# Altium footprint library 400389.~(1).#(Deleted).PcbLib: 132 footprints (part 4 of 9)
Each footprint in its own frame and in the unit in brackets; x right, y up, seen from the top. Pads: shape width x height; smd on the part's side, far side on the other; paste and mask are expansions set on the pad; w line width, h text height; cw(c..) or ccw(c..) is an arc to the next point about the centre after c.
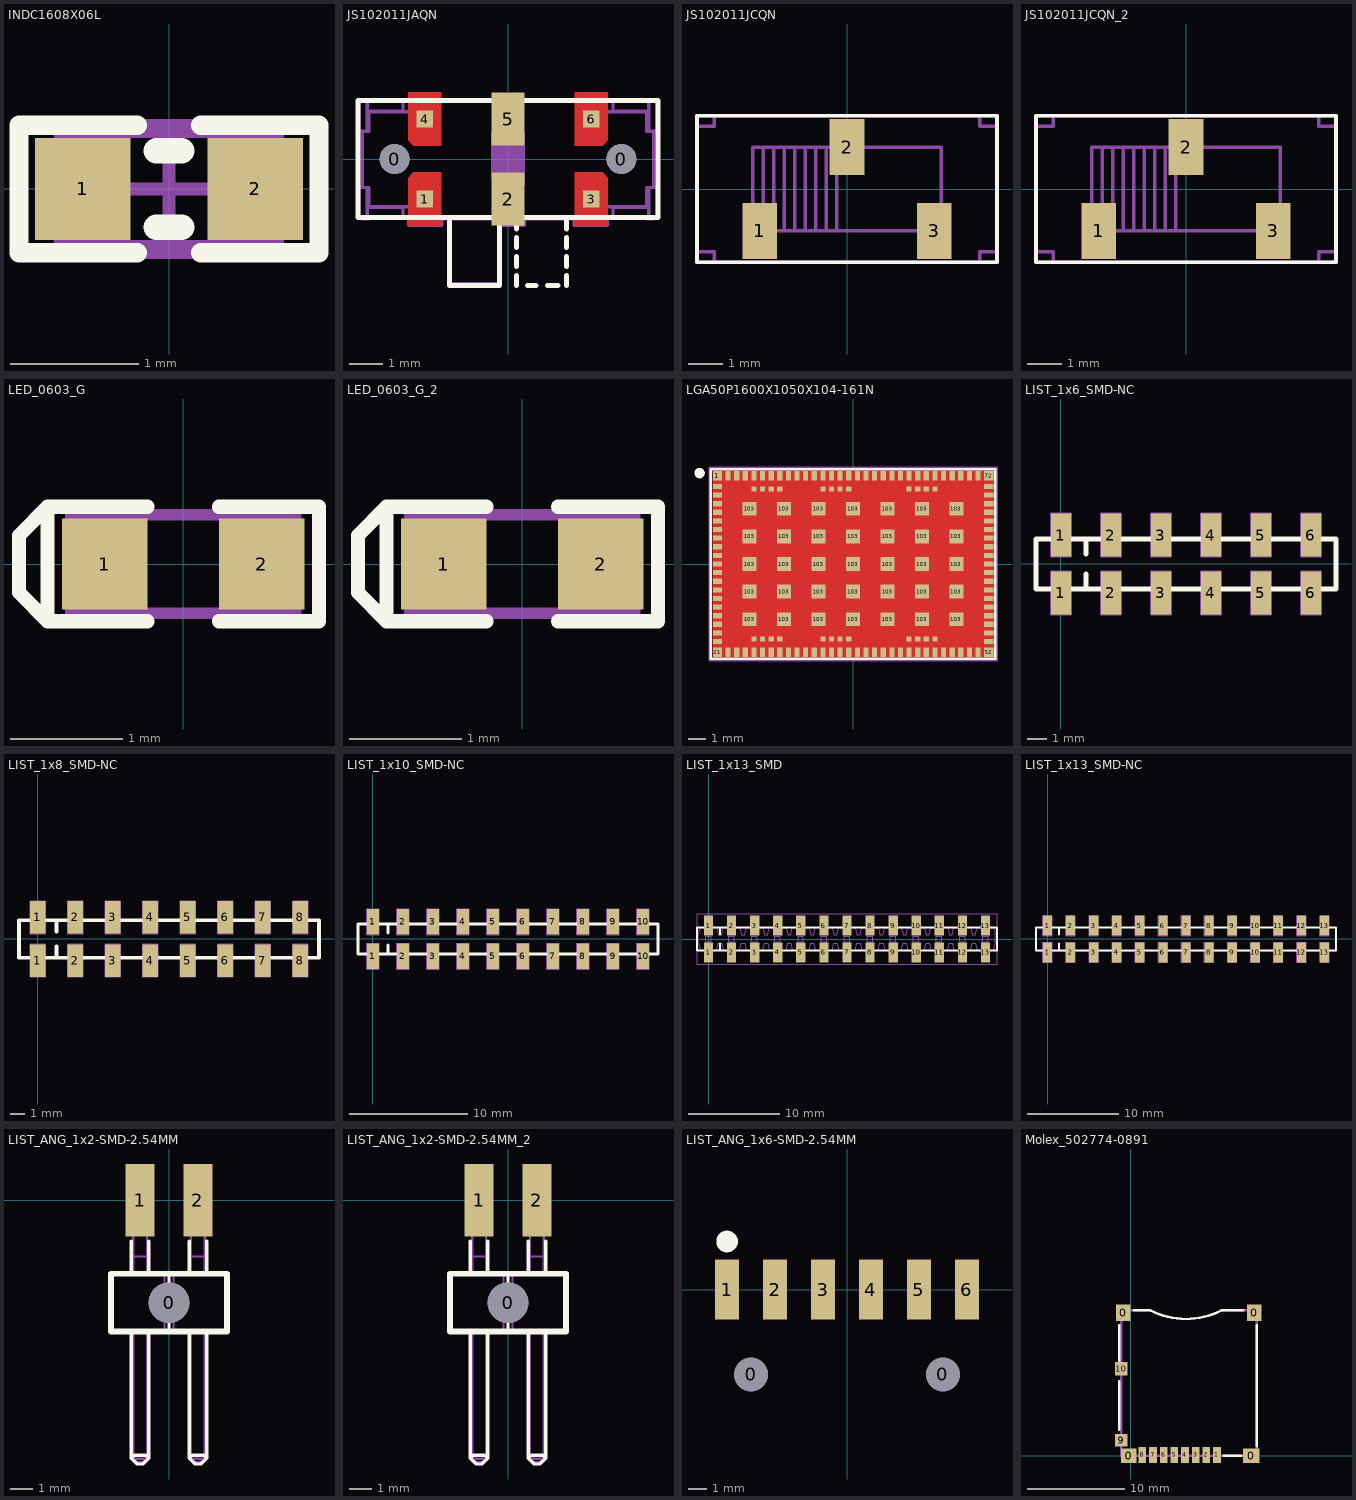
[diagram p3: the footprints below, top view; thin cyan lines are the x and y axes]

## INDC1608X06L [mm]
pads (2):
  rect 0.75x0.8 smd: 1(-0.675,0) 2(0.675,0)
Top Overlay:
  lines w0.152: -0.25,-0.5 -1.175,-0.5 -1.175,0.5 -0.25,0.5 ; 0.25,-0.5 1.175,-0.5 1.175,0.5 0.25,0.5
  lines w0.2: -0.1,-0.3 0.1,-0.3 ; -0.1,0.3 0.1,0.3
Mechanical 7:
  lines w0.1: -0.85,-0.45 0.85,-0.45 0.85,0.45 -0.85,0.45 -0.85,-0.45
  text ".Designator" at -0.711,-0.152 h0.3
Mechanical 15:
  lines w0.1: -0.45,0 0.45,0 ; 0,-0.45 0,0.45 ; -1.175,-0.5 -1.175,0.5 1.175,0.5 1.175,-0.5 -1.175,-0.5
3D body "User Library-Chip Inductor.step": height 0.8, standoff 0, extent -0.8,-0.475 0.8,0.475

## JS102011JAQN [mm]
pads (8):
  round 0.9 hole 0.9 unplated mask+0: 0(-3.4,0) 0(3.4,0)
  rect 0.5x0.5 smd: 1(-2.5,-1.2) 3(2.5,-1.2) 4(-2.5,1.2) 6(2.5,1.2)
  rect 1x1.6 smd: 2(0,-1.2) 5(0,1.2)
Top Layer:
  region: -3,0.562 -2.838,0.4 -2,0.4 -2,2 -3,2
  region: -3,-0.562 -2.838,-0.4 -2,-0.4 -2,-2 -3,-2
  region: 3,0.562 2.838,0.4 2,0.4 2,2 3,2
  region: 3,-0.562 2.838,-0.4 2,-0.4 2,-2 3,-2
Top Overlay:
  lines w0.152: -1.75,-1.75 -1.75,-3.8 -0.25,-3.8 -0.25,-1.75 ; 0.25,-3.8 0.25,-3.5 ; 0.25,-3.22 0.25,-2.92 ; 0.25,-2.66 0.25,-2.36 ; 0.25,-2.1 0.25,-1.75 ; 0.59,-3.8 0.84,-3.8 ; 1.19,-3.8 1.44,-3.8 ; 1.2,-3.8 1.5,-3.8 ; 1.75,-3.8 1.75,-3.5 ; 1.75,-3.22 1.75,-2.92 ; 1.75,-2.66 1.75,-2.36 ; 1.75,-2.1 1.75,-1.75 ; -4.5,-1.75 -4.5,1.75 4.5,1.75 4.5,-1.75 -4.5,-1.75
Mechanical 7:
  region: -0.5,-0.554 -0.254,-0.8 0.5,-0.8 0.5,0.8 -0.5,0.8
  lines w0.1: -4.376,-1.747 -4.376,-1.797 -4.174,-1.797 -4.174,-1.747 ; -4.376,1.731 -4.376,1.781 -4.174,1.781 -4.174,1.731 ; -4.224,-1.747 -4.224,-0.853 ; -4.224,-1.449 -3.151,-1.449 -3.151,-1.747 ; -4.224,0.836 -4.224,1.731 ; -4.224,1.433 -3.151,1.433 -3.151,1.731 ; -2.982,-1.747 -2.982,-1.996 -1.988,-1.996 -1.988,-1.797 ; -2.783,-1.747 -2.783,-1.797 -2.772,-1.797 ; -2.783,1.731 -2.783,1.781 -2.772,1.781 ; -2.772,-1.747 -4.472,-1.747 -4.472,-0.853 -4.376,-0.853 ; -2.772,1.731 -4.472,1.731 -4.472,0.836 -4.376,0.836 ; -1.74,-1.797 -1.74,-3.735 -0.249,-3.735 -0.249,-1.797 ; -0.249,-1.996 0.496,-1.996 0.496,-1.797 ; 1.987,-1.797 1.987,-1.996 2.981,-1.996 2.981,-1.747 ; 2.77,-1.747 4.471,-1.747 4.471,-0.853 4.375,-0.853 ; 2.77,1.731 4.471,1.731 4.471,0.836 4.375,0.836 ; 2.782,-1.747 2.782,-1.797 2.77,-1.797 ; 2.782,1.731 2.782,1.781 2.77,1.781 ; 3.149,-1.747 3.149,-1.449 4.223,-1.449 ; 3.149,1.731 3.149,1.433 4.223,1.433 ; 4.173,-1.747 4.173,-1.797 4.375,-1.797 4.375,-1.747 ; 4.173,1.731 4.173,1.781 4.375,1.781 4.375,1.731 ; 4.223,-1.747 4.223,-0.853 ; 4.223,0.836 4.223,1.731 ; -4.376,-0.853 -4.376,0.836 ; -4.376,-0.853 -4.168,-0.853 -4.168,-1.434 -2.772,-1.434 -2.772,-1.797 ; -4.376,0.836 -4.168,0.836 -4.168,1.418 -2.772,1.418 -2.772,1.781 ; -2.772,-1.797 2.77,-1.797 ; -2.772,1.781 2.77,1.781 ; 2.77,-1.797 2.77,-1.434 4.166,-1.434 4.166,-0.853 4.375,-0.853 ; 2.77,1.781 2.77,1.418 4.166,1.418 4.166,0.836 4.375,0.836 ; 4.375,-0.853 4.375,0.836
  text ".Designator" at -0.9,-0.2 h0.38
3D body "CL-SB-22A-11T.stp": height 3.5, standoff 0, extent -4.25,-3.75 4.25,1.75

## JS102011JCQN [mm]
pads (3):
  rect 1x1.6 smd: 1(-2.5,-1.2) 2(0,1.2) 3(2.5,-1.2)
Top Overlay:
  lines w0.102: -4.3,-2.1 4.3,-2.1 4.3,2.1 -4.3,2.1 -4.3,-2.1
Mechanical 7:
  lines w0.1: -4.3,-1.8 -3.8,-1.8 -3.8,-2.1 ; -4.3,1.8 -3.8,1.8 -3.8,2.1 ; 3.8,-2.1 3.8,-1.8 4.3,-1.8 ; 3.8,2.1 3.8,1.8 4.3,1.8
  lines w0.102: -4.3,-1.8 -4.3,1.8 ; -3.8,-2.1 3.8,-2.1 ; -3.8,2.1 3.8,2.1 ; -2.4,-1.2 -2.4,1.2 ; -2.1,-1.2 -2.1,1.2 ; -1.8,-1.2 -1.8,1.2 ; -1.5,-1.2 -1.5,1.2 ; -1.2,-1.2 -1.2,1.2 ; -0.9,-1.2 -0.9,1.2 ; -0.6,-1.2 -0.6,1.2 ; -0.3,-1.2 -0.3,1.2 ; 4.3,-1.8 4.3,1.8 ; -2.7,-1.2 2.7,-1.2 2.7,1.2 -2.7,1.2 -2.7,-1.2
  text ".Designator" at -1.7,-0.3 h0.76
Mechanical 15:
  lines w0.102: -4.3,-2.1 4.3,-2.1 4.3,2.1 -4.3,2.1 -4.3,-2.1
3D body "js102011jcqn.stp": height 5.22, standoff -0.38, extent -4.25,-2.05 4.25,2.05

## JS102011JCQN_2 [mm]
pads (3):
  rect 1x1.6 smd: 1(-2.5,-1.2) 2(0,1.2) 3(2.5,-1.2)
Top Overlay:
  lines w0.102: -4.3,-2.1 4.3,-2.1 4.3,2.1 -4.3,2.1 -4.3,-2.1
Mechanical 7:
  lines w0.1: -4.3,-1.8 -3.8,-1.8 -3.8,-2.1 ; -4.3,1.8 -3.8,1.8 -3.8,2.1 ; 3.8,-2.1 3.8,-1.8 4.3,-1.8 ; 3.8,2.1 3.8,1.8 4.3,1.8
  lines w0.102: -4.3,-1.8 -4.3,1.8 ; -3.8,-2.1 3.8,-2.1 ; -3.8,2.1 3.8,2.1 ; -2.4,-1.2 -2.4,1.2 ; -2.1,-1.2 -2.1,1.2 ; -1.8,-1.2 -1.8,1.2 ; -1.5,-1.2 -1.5,1.2 ; -1.2,-1.2 -1.2,1.2 ; -0.9,-1.2 -0.9,1.2 ; -0.6,-1.2 -0.6,1.2 ; -0.3,-1.2 -0.3,1.2 ; 4.3,-1.8 4.3,1.8 ; -2.7,-1.2 2.7,-1.2 2.7,1.2 -2.7,1.2 -2.7,-1.2
  text ".Designator" at -1.7,-0.3 h0.76
Mechanical 15:
  lines w0.102: -4.3,-2.1 4.3,-2.1 4.3,2.1 -4.3,2.1 -4.3,-2.1
3D body "js102011jcqn.stp": height 5.22, standoff -0.38, extent -4.25,-2.05 4.25,2.05

## LED_0603_G [mil]
pads (2):
  rect 30x32 smd: 1(-27.5,0) 2(27.5,0)
Top Overlay:
  lines w5: -12.5,-20 -47.5,-20 ; -12.5,20 -47.5,20 ; 12.5,-20 47.5,-20 47.5,20 12.5,20 ; -47.5,-20 -57.5,-10 -57.5,10 -47.5,20 ; -47.5,-20 -47.5,20
Mechanical 7:
  lines w3.94: -27.56,-17.26 -27.56,17.26 ; -23.62,-17.26 -23.62,17.26 ; 23.62,-17.26 23.62,17.26 ; 27.56,-17.26 27.56,17.26 ; -39.37,-17.26 -39.37,17.26 39.37,17.26 39.37,-17.26 -39.37,-17.26
  text ".Designator" at -19.68,-4.92 h12
3D body "User Library-led_0603_green.step": height 23.62, standoff 0, extent -31.63,-15.75 32.15,15.75

## LED_0603_G_2 [mil]
pads (2):
  rect 30x32 smd: 1(-27.5,0) 2(27.5,0)
Top Overlay:
  lines w5: -12.5,-20 -47.5,-20 ; -12.5,20 -47.5,20 ; 12.5,-20 47.5,-20 47.5,20 12.5,20 ; -47.5,-20 -57.5,-10 -57.5,10 -47.5,20 ; -47.5,-20 -47.5,20
Mechanical 7:
  lines w3.94: -27.56,-17.26 -27.56,17.26 ; -23.62,-17.26 -23.62,17.26 ; 23.62,-17.26 23.62,17.26 ; 27.56,-17.26 27.56,17.26 ; -39.37,-17.26 -39.37,17.26 39.37,17.26 39.37,-17.26 -39.37,-17.26
  text ".Designator" at -19.68,-4.92 h12
3D body "User Library-led_0603_green.step": height 23.62, standoff 0, extent -31.63,-15.75 32.15,15.75

## LGA50P1600X1050X104-161N [mm]
pads (161):
  rect 0.54x0.54 smd mask+0.05: 1(-7.87,5.12) 21(-7.87,-5.12) 52(7.87,-5.12) 72(7.87,5.12)
  rect 0.54x0.3 smd mask+0.05: 2(-7.87,4.5) 3(-7.87,4) 4(-7.87,3.5) 5(-7.87,3) 6(-7.87,2.5) 7(-7.87,2) 8(-7.87,1.5) 9(-7.87,1) 10(-7.87,0.5) 11(-7.87,0) 12(-7.87,-0.5) 13(-7.87,-1) 14(-7.87,-1.5) 15(-7.87,-2) 16(-7.87,-2.5) 17(-7.87,-3) 18(-7.87,-3.5) 19(-7.87,-4) 20(-7.87,-4.5) 53(7.87,-4.5) 54(7.87,-4) 55(7.87,-3.5) 56(7.87,-3) 57(7.87,-2.5) 58(7.87,-2) 59(7.87,-1.5) 60(7.87,-1) 61(7.87,-0.5) 62(7.87,0) 63(7.87,0.5) 64(7.87,1) 65(7.87,1.5) 66(7.87,2) 67(7.87,2.5) 68(7.87,3) 69(7.87,3.5) 70(7.87,4) 71(7.87,4.5)
  rect 0.3x0.54 smd mask+0.05: 22(-7.25,-5.12) 23(-6.75,-5.12) 24(-6.25,-5.12) 25(-5.75,-5.12) 26(-5.25,-5.12) 27(-4.75,-5.12) 28(-4.25,-5.12) 29(-3.75,-5.12) 30(-3.25,-5.12) 31(-2.75,-5.12) 32(-2.25,-5.12) 33(-1.75,-5.12) 34(-1.25,-5.12) 35(-0.75,-5.12) 36(-0.25,-5.12) 37(0.25,-5.12) 38(0.75,-5.12) 39(1.25,-5.12) 40(1.75,-5.12) 41(2.25,-5.12) 42(2.75,-5.12) 43(3.25,-5.12) 44(3.75,-5.12) 45(4.25,-5.12) 46(4.75,-5.12) 47(5.25,-5.12) 48(5.75,-5.12) 49(6.25,-5.12) 50(6.75,-5.12) 51(7.25,-5.12) 73(7.25,5.12) 74(6.75,5.12) 75(6.25,5.12) 76(5.75,5.12) 77(5.25,5.12) 78(4.75,5.12) 79(4.25,5.12) 80(3.75,5.12) 81(3.25,5.12) 82(2.75,5.12) 83(2.25,5.12) 84(1.75,5.12) 85(1.25,5.12) 86(0.75,5.12) 87(0.25,5.12) 88(-0.25,5.12) 89(-0.75,5.12) 90(-1.25,5.12) 91(-1.75,5.12) 92(-2.25,5.12) 93(-2.75,5.12) 94(-3.25,5.12) 95(-3.75,5.12) 96(-4.25,5.12) 97(-4.75,5.12) 98(-5.25,5.12) 99(-5.75,5.12) 100(-6.25,5.12) 101(-6.75,5.12) 102(-7.25,5.12)
  rect 0.8x0.8 smd mask+0.05: 103(-6,-3.2) 103(-6,-1.6) 103(-6,0) 103(-6,1.6) 103(-6,3.2) 103(-4,-3.2) 103(-4,-1.6) 103(-4,0) 103(-4,1.6) 103(-4,3.2) 103(-2,-3.2) 103(-2,-1.6) 103(-2,0) 103(-2,1.6) 103(-2,3.2) 103(0,-3.2) 103(0,-1.6) 103(0,0) 103(0,1.6) 103(0,3.2) 103(2,-3.2) 103(2,-1.6) 103(2,0) 103(2,1.6) 103(2,3.2) 103(4,-3.2) 103(4,-1.6) 103(4,0) 103(4,1.6) 103(4,3.2) 103(6,-3.2) 103(6,-1.6) 103(6,0) 103(6,1.6) 103(6,3.2)
  rect 0.3x0.3 smd mask+0.05: 104(-5.75,-4.35) 105(-5.25,-4.35) 106(-4.75,-4.35) 107(-4.25,-4.35) 108(-1.75,-4.35) 109(-1.25,-4.35) 110(-0.75,-4.35) 111(-0.25,-4.35) 112(3.25,-4.35) 113(3.75,-4.35) 114(4.25,-4.35) 115(4.75,-4.35) 116(4.75,4.35) 117(4.25,4.35) 118(3.75,4.35) 119(3.25,4.35) 120(-0.25,4.35) 121(-0.75,4.35) 122(-1.25,4.35) 123(-1.75,4.35) 124(-4.25,4.35) 125(-4.75,4.35) 126(-5.25,4.35) 127(-5.75,4.35)
Top Layer:
  pour cut-out: -8.15,5.4 8.15,5.4 8.15,-5.4 -8.15,-5.4
Top Overlay:
  circle w0.3: c-8.904,5.274 r0.15
  lines w0.15: -8.25,-5.5 -8.25,5.5 8.25,5.5 8.25,-5.5 -8.25,-5.5
Mechanical 7:
  circle w0.3: c-6.5,3.75 r0.15
  lines w0.1: -8.05,-5.3 -8.05,5.3 8.05,5.3 8.05,-5.3 -8.05,-5.3
  text ".Designator" at 0.5,-0.1 h0.38
Mechanical 15:
  circle w0.3: c-6.5,3.75 r0.15
  lines w0.1: -8.35,-5.6 8.35,-5.6 8.35,5.6 -8.35,5.6 -8.35,-5.6
3D body "nRF9160_v5.step": height 1.2, standoff 0, extent -8.05,-5.3 8.05,5.3

## LIST_1x6_SMD-NC [mm]
pads (12):
  rect 1.02x2.19 smd: 1(0,-1.465) 1(0,1.465) 2(2.54,-1.465) 2(2.54,1.465) 3(5.08,-1.465) 3(5.08,1.465) 4(7.62,-1.465) 4(7.62,1.465) 5(10.16,-1.465) 5(10.16,1.465) 6(12.7,-1.465) 6(12.7,1.465)
Top Overlay:
  lines w0.254: 1.27,-1.27 1.27,-0.508 ; 1.27,0.508 1.27,1.27 ; -1.27,-1.27 -1.27,1.27 13.97,1.27 13.97,-1.27 -1.27,-1.27
Mechanical 7:
  lines w0.1: -0.686,-1.27 -1.27,-1.27 -1.27,1.27 -0.686,1.27 ; 0.686,-1.27 1.854,-1.27 ; 0.686,1.27 1.854,1.27 ; 1.27,-1.27 1.27,-0.508 ; 1.27,0.508 1.27,1.27 ; 3.226,-1.27 4.394,-1.27 ; 3.226,1.27 4.394,1.27 ; 5.766,-1.27 6.934,-1.27 ; 5.766,1.27 6.934,1.27 ; 8.306,-1.27 9.474,-1.27 ; 8.306,1.27 9.474,1.27 ; 10.846,-1.27 12.014,-1.27 ; 10.846,1.27 12.014,1.27 ; 13.386,-1.27 13.97,-1.27 13.97,1.27 13.386,1.27 ; -0.51,-2.56 -0.51,-0.37 0.51,-0.37 0.51,-2.56 -0.51,-2.56 ; -0.51,0.37 0.51,0.37 0.51,2.56 -0.51,2.56 -0.51,0.37 ; 2.03,-2.56 2.03,-0.37 3.05,-0.37 3.05,-2.56 2.03,-2.56 ; 2.03,0.37 2.03,2.56 3.05,2.56 3.05,0.37 2.03,0.37 ; 4.57,-2.56 4.57,-0.37 5.59,-0.37 5.59,-2.56 4.57,-2.56 ; 4.57,0.37 4.57,2.56 5.59,2.56 5.59,0.37 4.57,0.37 ; 7.11,-2.56 7.11,-0.37 8.13,-0.37 8.13,-2.56 7.11,-2.56 ; 7.11,0.37 7.11,2.56 8.13,2.56 8.13,0.37 7.11,0.37 ; 9.65,-2.56 9.65,-0.37 10.67,-0.37 10.67,-2.56 9.65,-2.56 ; 9.65,0.37 9.65,2.56 10.67,2.56 10.67,0.37 9.65,0.37 ; 12.19,-2.56 12.19,-0.37 13.21,-0.37 13.21,-2.56 12.19,-2.56 ; 12.19,0.37 12.19,2.56 13.21,2.56 13.21,0.37 12.19,0.37
  text ".Designator" at 0.5,-0.2 h0.38

## LIST_1x8_SMD-NC [mm]
pads (16):
  rect 1.02x2.19 smd: 1(0,-1.465) 1(0,1.465) 2(2.54,-1.465) 2(2.54,1.465) 3(5.08,-1.465) 3(5.08,1.465) 4(7.62,-1.465) 4(7.62,1.465) 5(10.16,-1.465) 5(10.16,1.465) 6(12.7,-1.465) 6(12.7,1.465) 7(15.24,-1.465) 7(15.24,1.465) 8(17.78,-1.465) 8(17.78,1.465)
Top Overlay:
  lines w0.254: 1.27,-1.27 1.27,-0.508 ; 1.27,0.508 1.27,1.27 ; -1.27,-1.27 19.05,-1.27 19.05,1.27 -1.27,1.27 -1.27,-1.27
Mechanical 7:
  lines w0.1: -0.686,-1.27 -1.27,-1.27 -1.27,1.27 -0.686,1.27 ; 0.686,-1.27 1.854,-1.27 ; 0.686,1.27 1.854,1.27 ; 1.27,-1.27 1.27,-0.508 ; 1.27,0.508 1.27,1.27 ; 3.226,-1.27 4.394,-1.27 ; 3.226,1.27 4.394,1.27 ; 5.766,-1.27 6.934,-1.27 ; 5.766,1.27 6.934,1.27 ; 8.306,-1.27 9.474,-1.27 ; 8.306,1.27 9.474,1.27 ; 10.846,-1.27 12.014,-1.27 ; 10.846,1.27 12.014,1.27 ; 13.386,-1.27 14.554,-1.27 ; 13.386,1.27 14.554,1.27 ; 15.926,-1.27 17.094,-1.27 ; 15.926,1.27 17.094,1.27 ; 18.466,-1.27 19.05,-1.27 19.05,1.27 18.466,1.27 ; -0.51,-2.56 0.51,-2.56 0.51,-0.37 -0.51,-0.37 -0.51,-2.56 ; -0.51,0.37 -0.51,2.56 0.51,2.56 0.51,0.37 -0.51,0.37 ; 2.03,-2.56 3.05,-2.56 3.05,-0.37 2.03,-0.37 2.03,-2.56 ; 2.03,0.37 3.05,0.37 3.05,2.56 2.03,2.56 2.03,0.37 ; 4.57,-2.56 5.59,-2.56 5.59,-0.37 4.57,-0.37 4.57,-2.56 ; 4.57,0.37 5.59,0.37 5.59,2.56 4.57,2.56 4.57,0.37 ; 7.11,-2.56 8.13,-2.56 8.13,-0.37 7.11,-0.37 7.11,-2.56 ; 7.11,0.37 8.13,0.37 8.13,2.56 7.11,2.56 7.11,0.37 ; 9.65,-2.56 10.67,-2.56 10.67,-0.37 9.65,-0.37 9.65,-2.56 ; 9.65,0.37 10.67,0.37 10.67,2.56 9.65,2.56 9.65,0.37 ; 12.19,-2.56 13.21,-2.56 13.21,-0.37 12.19,-0.37 12.19,-2.56 ; 12.19,0.37 13.21,0.37 13.21,2.56 12.19,2.56 12.19,0.37 ; 14.73,-2.56 15.75,-2.56 15.75,-0.37 14.73,-0.37 14.73,-2.56 ; 14.73,0.37 15.75,0.37 15.75,2.56 14.73,2.56 14.73,0.37 ; 17.27,-2.56 18.29,-2.56 18.29,-0.37 17.27,-0.37 17.27,-2.56 ; 17.27,0.37 18.29,0.37 18.29,2.56 17.27,2.56 17.27,0.37
  text ".Designator" at 0.5,-0.2 h0.38

## LIST_1x10_SMD-NC [mm]
pads (20):
  rect 1.02x2.19 smd: 1(0,-1.465) 1(0,1.465) 2(2.54,-1.465) 2(2.54,1.465) 3(5.08,-1.465) 3(5.08,1.465) 4(7.62,-1.465) 4(7.62,1.465) 5(10.16,-1.465) 5(10.16,1.465) 6(12.7,-1.465) 6(12.7,1.465) 7(15.24,-1.465) 7(15.24,1.465) 8(17.78,-1.465) 8(17.78,1.465) 9(20.32,-1.465) 9(20.32,1.465) 10(22.86,-1.465) 10(22.86,1.465)
Top Overlay:
  lines w0.254: 1.27,-1.27 1.27,-0.508 ; 1.27,0.508 1.27,1.27 ; -1.27,-1.27 -1.27,1.27 24.13,1.27 24.13,-1.27 -1.27,-1.27
Mechanical 7:
  lines w0.1: -0.686,-1.27 -1.27,-1.27 -1.27,1.27 -0.686,1.27 ; 0.686,-1.27 1.854,-1.27 ; 0.686,1.27 1.854,1.27 ; 1.27,-1.27 1.27,-0.508 ; 1.27,0.508 1.27,1.27 ; 3.226,-1.27 4.394,-1.27 ; 3.226,1.27 4.394,1.27 ; 5.766,-1.27 6.934,-1.27 ; 5.766,1.27 6.934,1.27 ; 8.306,-1.27 9.474,-1.27 ; 8.306,1.27 9.474,1.27 ; 10.846,-1.27 12.014,-1.27 ; 10.846,1.27 12.014,1.27 ; 13.386,-1.27 14.554,-1.27 ; 13.386,1.27 14.554,1.27 ; 15.926,-1.27 17.094,-1.27 ; 15.926,1.27 17.094,1.27 ; 18.466,-1.27 19.634,-1.27 ; 18.466,1.27 19.634,1.27 ; 21.006,-1.27 22.174,-1.27 ; 21.006,1.27 22.174,1.27 ; 23.546,-1.27 24.13,-1.27 24.13,1.27 23.546,1.27 ; -0.51,-2.56 -0.51,-0.37 0.51,-0.37 0.51,-2.56 -0.51,-2.56 ; -0.51,0.37 0.51,0.37 0.51,2.56 -0.51,2.56 -0.51,0.37 ; 2.03,-2.56 2.03,-0.37 3.05,-0.37 3.05,-2.56 2.03,-2.56 ; 2.03,0.37 2.03,2.56 3.05,2.56 3.05,0.37 2.03,0.37 ; 4.57,-2.56 4.57,-0.37 5.59,-0.37 5.59,-2.56 4.57,-2.56 ; 4.57,0.37 4.57,2.56 5.59,2.56 5.59,0.37 4.57,0.37 ; 7.11,-2.56 7.11,-0.37 8.13,-0.37 8.13,-2.56 7.11,-2.56 ; 7.11,0.37 7.11,2.56 8.13,2.56 8.13,0.37 7.11,0.37 ; 9.65,-2.56 9.65,-0.37 10.67,-0.37 10.67,-2.56 9.65,-2.56 ; 9.65,0.37 9.65,2.56 10.67,2.56 10.67,0.37 9.65,0.37 ; 12.19,-2.56 12.19,-0.37 13.21,-0.37 13.21,-2.56 12.19,-2.56 ; 12.19,0.37 12.19,2.56 13.21,2.56 13.21,0.37 12.19,0.37 ; 14.73,-2.56 14.73,-0.37 15.75,-0.37 15.75,-2.56 14.73,-2.56 ; 14.73,0.37 14.73,2.56 15.75,2.56 15.75,0.37 14.73,0.37 ; 17.27,-2.56 17.27,-0.37 18.29,-0.37 18.29,-2.56 17.27,-2.56 ; 17.27,0.37 17.27,2.56 18.29,2.56 18.29,0.37 17.27,0.37 ; 19.81,-2.56 20.83,-2.56 20.83,-0.37 19.81,-0.37 19.81,-2.56 ; 19.81,0.37 20.83,0.37 20.83,2.56 19.81,2.56 19.81,0.37 ; 22.35,-2.56 23.37,-2.56 23.37,-0.37 22.35,-0.37 22.35,-2.56 ; 22.35,0.37 23.37,0.37 23.37,2.56 22.35,2.56 22.35,0.37
  text ".Designator" at 0.5,-0.2 h0.38

## LIST_1x13_SMD [mm]
pads (26):
  rect 1.02x2.19 smd: 1(0,-1.465) 1(0,1.465) 2(2.54,-1.465) 2(2.54,1.465) 3(5.08,-1.465) 3(5.08,1.465) 4(7.62,-1.465) 4(7.62,1.465) 5(10.16,-1.465) 5(10.16,1.465) 6(12.7,-1.465) 6(12.7,1.465) 7(15.24,-1.465) 7(15.24,1.465) 8(17.78,-1.465) 8(17.78,1.465) 9(20.32,-1.465) 9(20.32,1.465) 10(22.86,-1.465) 10(22.86,1.465) 11(25.4,-1.465) 11(25.4,1.465) 12(27.94,-1.465) 12(27.94,1.465) 13(30.48,-1.465) 13(30.48,1.465)
Top Overlay:
  lines w0.254: 1.27,-1.27 1.27,-0.508 ; 1.27,0.508 1.27,1.27 ; -1.27,-1.27 31.75,-1.27 31.75,1.27 -1.27,1.27 -1.27,-1.27
Mechanical 7:
  drawing of 195 lines, arcs and shapes, not listed
  text ".Designator" at 0.5,-0.2 h0.38
Mechanical 15:
  lines w0.1: -1.27,-2.8 -1.27,2.8 31.75,2.8 31.75,-2.8 -1.27,-2.8
3D body "pin_header_a-sl254-eg-g13mp1.stp": height 9.82, standoff -0.02, extent -1.27,-2.5 31.75,2.5

## LIST_1x13_SMD-NC [mm]
pads (26):
  rect 1.02x2.19 smd: 1(0,-1.465) 1(0,1.465) 2(2.54,-1.465) 2(2.54,1.465) 3(5.08,-1.465) 3(5.08,1.465) 4(7.62,-1.465) 4(7.62,1.465) 5(10.16,-1.465) 5(10.16,1.465) 6(12.7,-1.465) 6(12.7,1.465) 7(15.24,-1.465) 7(15.24,1.465) 8(17.78,-1.465) 8(17.78,1.465) 9(20.32,-1.465) 9(20.32,1.465) 10(22.86,-1.465) 10(22.86,1.465) 11(25.4,-1.465) 11(25.4,1.465) 12(27.94,-1.465) 12(27.94,1.465) 13(30.48,-1.465) 13(30.48,1.465)
Top Overlay:
  lines w0.254: 1.27,-1.27 1.27,-0.508 ; 1.27,0.508 1.27,1.27 ; -1.27,-1.27 31.75,-1.27 31.75,1.27 -1.27,1.27 -1.27,-1.27
Mechanical 7:
  lines w0.1: -0.686,-1.27 -1.27,-1.27 -1.27,1.27 -0.686,1.27 ; 0.686,-1.27 1.854,-1.27 ; 0.686,1.27 1.854,1.27 ; 1.27,-1.27 1.27,-0.508 ; 1.27,0.508 1.27,1.27 ; 3.226,-1.27 4.394,-1.27 ; 3.226,1.27 4.394,1.27 ; 5.766,-1.27 6.934,-1.27 ; 5.766,1.27 6.934,1.27 ; 8.306,-1.27 9.474,-1.27 ; 8.306,1.27 9.474,1.27 ; 10.846,-1.27 12.014,-1.27 ; 10.846,1.27 12.014,1.27 ; 13.386,-1.27 14.554,-1.27 ; 13.386,1.27 14.554,1.27 ; 15.926,-1.27 17.094,-1.27 ; 15.926,1.27 17.094,1.27 ; 18.466,-1.27 19.634,-1.27 ; 18.466,1.27 19.634,1.27 ; 21.006,-1.27 22.174,-1.27 ; 21.006,1.27 22.174,1.27 ; 23.546,-1.27 24.714,-1.27 ; 23.546,1.27 24.714,1.27 ; 26.086,-1.27 27.254,-1.27 ; 26.086,1.27 27.254,1.27 ; 28.626,-1.27 29.794,-1.27 ; 28.626,1.27 29.794,1.27 ; 31.166,-1.27 31.75,-1.27 31.75,1.27 31.166,1.27 ; -0.51,-2.56 0.51,-2.56 0.51,-0.37 -0.51,-0.37 -0.51,-2.56 ; -0.51,0.37 -0.51,2.56 0.51,2.56 0.51,0.37 -0.51,0.37 ; 2.03,-2.56 3.05,-2.56 3.05,-0.37 2.03,-0.37 2.03,-2.56 ; 2.03,0.37 3.05,0.37 3.05,2.56 2.03,2.56 2.03,0.37 ; 4.57,-2.56 5.59,-2.56 5.59,-0.37 4.57,-0.37 4.57,-2.56 ; 4.57,0.37 5.59,0.37 5.59,2.56 4.57,2.56 4.57,0.37 ; 7.11,-2.56 8.13,-2.56 8.13,-0.37 7.11,-0.37 7.11,-2.56 ; 7.11,0.37 8.13,0.37 8.13,2.56 7.11,2.56 7.11,0.37 ; 9.65,-2.56 10.67,-2.56 10.67,-0.37 9.65,-0.37 9.65,-2.56 ; 9.65,0.37 10.67,0.37 10.67,2.56 9.65,2.56 9.65,0.37 ; 12.19,-2.56 13.21,-2.56 13.21,-0.37 12.19,-0.37 12.19,-2.56 ; 12.19,0.37 13.21,0.37 13.21,2.56 12.19,2.56 12.19,0.37 ; 14.73,-2.56 15.75,-2.56 15.75,-0.37 14.73,-0.37 14.73,-2.56 ; 14.73,0.37 15.75,0.37 15.75,2.56 14.73,2.56 14.73,0.37 ; 17.27,-2.56 18.29,-2.56 18.29,-0.37 17.27,-0.37 17.27,-2.56 ; 17.27,0.37 18.29,0.37 18.29,2.56 17.27,2.56 17.27,0.37 ; 19.81,-2.56 19.81,-0.37 20.83,-0.37 20.83,-2.56 19.81,-2.56 ; 19.81,0.37 19.81,2.56 20.83,2.56 20.83,0.37 19.81,0.37 ; 22.35,-2.56 22.35,-0.37 23.37,-0.37 23.37,-2.56 22.35,-2.56 ; 22.35,0.37 22.35,2.56 23.37,2.56 23.37,0.37 22.35,0.37 ; 24.89,-2.56 24.89,-0.37 25.91,-0.37 25.91,-2.56 24.89,-2.56 ; 24.89,0.37 24.89,2.56 25.91,2.56 25.91,0.37 24.89,0.37 ; 27.43,-2.56 27.43,-0.37 28.45,-0.37 28.45,-2.56 27.43,-2.56 ; 27.43,0.37 27.43,2.56 28.45,2.56 28.45,0.37 27.43,0.37 ; 29.97,-2.56 30.99,-2.56 30.99,-0.37 29.97,-0.37 29.97,-2.56 ; 29.97,0.37 30.99,0.37 30.99,2.56 29.97,2.56 29.97,0.37
  text ".Designator" at 0.5,-0.2 h0.38

## LIST_ANG_1x2-SMD-2.54MM [mm]
pads (3):
  round 1.78 hole 1.78 unplated: 0(0,-4.496)
  rect 1.27x3.18 smd: 1(-1.27,0) 2(1.27,0)
Top Overlay:
  lines w0.15: -1.651,-5.766 -1.651,-11.324 ; -1.651,-3.226 -1.651,-1.8 ; -0.889,-5.766 -0.889,-11.324 ; -0.889,-3.226 -0.889,-1.8 ; 0,-5.766 0,-3.226 ; 0.889,-5.766 0.889,-11.324 ; 0.889,-3.226 0.889,-1.8 ; 1.651,-5.766 1.651,-11.324 ; 1.651,-3.226 1.651,-1.8 ; -1.651,-11.324 -1.524,-11.197 -1.016,-11.197 -0.889,-11.324 ; -1.651,-11.324 -1.397,-11.578 -1.143,-11.578 -0.889,-11.324 ; 0.889,-11.324 1.016,-11.197 1.524,-11.197 1.651,-11.324 ; 0.889,-11.324 1.143,-11.578 1.397,-11.578 1.651,-11.324
  lines w0.254: -2.54,-5.766 2.54,-5.766 2.54,-3.226 -2.54,-3.226 -2.54,-5.766
Mechanical 7:
  lines w0.1: -1.57,-5.766 -1.57,-11.347 ; -1.57,-3.226 -1.57,0.85 ; -1.57,-2.466 -0.97,-2.466 ; -1.57,-0.464 -0.97,-0.464 ; -0.97,-5.766 -0.97,-11.347 ; -0.97,-3.226 -0.97,0.85 ; -0.2,-5.766 -0.2,-3.226 ; 0.2,-5.766 0.2,-3.226 ; 0.97,-5.766 0.97,-11.347 ; 0.97,-3.226 0.97,0.85 ; 0.97,-2.466 1.57,-2.466 ; 0.97,-0.464 1.57,-0.464 ; 1.57,-5.766 1.57,-11.347 ; 1.57,-3.226 1.57,0.85 ; -1.57,-11.347 -1.42,-11.497 -1.12,-11.497 -0.97,-11.347 ; -1.57,-11.347 -0.97,-11.347 ; -1.57,0.85 -1.42,1 -1.12,1 -0.97,0.85 ; -1.57,0.85 -0.97,0.85 ; 0.97,-11.347 1.12,-11.497 1.42,-11.497 1.57,-11.347 ; 0.97,-11.347 1.57,-11.347 ; 0.97,0.85 1.12,1 1.42,1 1.57,0.85 ; 0.97,0.85 1.57,0.85 ; -2.54,-5.766 2.54,-5.766 2.54,-3.226 -2.54,-3.226 -2.54,-5.766
  text ".Designator" at -2,-4.7 h0.38
3D body "Samtec-TSM-102-01-L-SH-A.step": height 3.03, standoff -1.41, extent -2.56,-11.605 2.52,1.349

## LIST_ANG_1x2-SMD-2.54MM_2 [mm]
pads (3):
  round 1.78 hole 1.78 unplated: 0(0,-4.496)
  rect 1.27x3.18 smd: 1(-1.27,0) 2(1.27,0)
Top Overlay:
  lines w0.15: -1.651,-5.766 -1.651,-11.324 ; -1.651,-3.226 -1.651,-1.8 ; -0.889,-5.766 -0.889,-11.324 ; -0.889,-3.226 -0.889,-1.8 ; 0,-5.766 0,-3.226 ; 0.889,-5.766 0.889,-11.324 ; 0.889,-3.226 0.889,-1.8 ; 1.651,-5.766 1.651,-11.324 ; 1.651,-3.226 1.651,-1.8 ; -1.651,-11.324 -1.397,-11.578 -1.143,-11.578 -0.889,-11.324 ; -1.651,-11.324 -1.524,-11.197 -1.016,-11.197 -0.889,-11.324 ; 0.889,-11.324 1.143,-11.578 1.397,-11.578 1.651,-11.324 ; 0.889,-11.324 1.016,-11.197 1.524,-11.197 1.651,-11.324
  lines w0.254: -2.54,-5.766 -2.54,-3.226 2.54,-3.226 2.54,-5.766 -2.54,-5.766
Mechanical 7:
  lines w0.1: -1.57,-5.766 -1.57,-11.347 ; -1.57,-3.226 -1.57,0.85 ; -1.57,-2.466 -0.97,-2.466 ; -1.57,-0.464 -0.97,-0.464 ; -0.97,-5.766 -0.97,-11.347 ; -0.97,-3.226 -0.97,0.85 ; -0.2,-5.766 -0.2,-3.226 ; 0.2,-5.766 0.2,-3.226 ; 0.97,-5.766 0.97,-11.347 ; 0.97,-3.226 0.97,0.85 ; 0.97,-2.466 1.57,-2.466 ; 0.97,-0.464 1.57,-0.464 ; 1.57,-5.766 1.57,-11.347 ; 1.57,-3.226 1.57,0.85 ; -1.57,-11.347 -0.97,-11.347 ; -1.57,-11.347 -1.42,-11.497 -1.12,-11.497 -0.97,-11.347 ; -1.57,0.85 -0.97,0.85 ; -1.57,0.85 -1.42,1 -1.12,1 -0.97,0.85 ; 0.97,-11.347 1.57,-11.347 ; 0.97,-11.347 1.12,-11.497 1.42,-11.497 1.57,-11.347 ; 0.97,0.85 1.57,0.85 ; 0.97,0.85 1.12,1 1.42,1 1.57,0.85 ; -2.54,-5.766 -2.54,-3.226 2.54,-3.226 2.54,-5.766 -2.54,-5.766
  text ".Designator" at -2,-4.7 h0.38
3D body "Samtec-TSM-102-01-L-SH-A.step": height 3.03, standoff -1.41, extent -2.56,-11.605 2.52,1.349

## LIST_ANG_1x6-SMD-2.54MM [mm]
pads (8):
  round 1.78 hole 1.78 unplated: 0(-5.08,-4.496) 0(5.08,-4.496)
  rect 1.27x3.18 smd: 1(-6.35,0) 2(-3.81,0) 3(-1.27,0) 4(1.27,0) 5(3.81,0) 6(6.35,0)
Top Overlay:
  circle w0.635: c-6.35,2.54 r0.254

## Molex_502774-0891 [mm]
pads (14):
  rect 1.5x1.7 smd mask+0.05: 0(-0.75,14.77) 0(12.75,14.77)
  rect 1.6x1.5 smd mask+0.05: 0(-0.21,0)
  rect 1.7x1.5 smd mask+0.05: 0(12.45,0)
  rect 0.8x1.68 smd mask+0.05: 1(8.9,0.08) 2(7.8,0.08) 3(6.7,0.08) 4(5.6,0.08) 5(4.5,0.08) 6(3.4,0.08) 7(2.3,0.08) 8(1.2,0.08)
  rect 1.29x1.3 smd mask+0.05: 9(-0.96,1.6)
  rect 1.29x1.4 smd mask+0.05: 10(-0.96,8.97)
Top Overlay:
  lines w0.254: -1.2,2.7 -1.2,7.7 ; -1.2,9.8 -1.2,13.5 ; 0.3,14.999 2,15 ; 2.091,14.981 ccw(c5.705,22.118) 9.311,14.977 ; 9.4,15 11.6,15 ; 9.6,0 11.4,0 ; 13,1 13,13.5
Mechanical 7:
  lines w0.254: 2.072,15 -1,15 -1,0 13,0 13,15 9.334,15 ; 2.091,14.981 ccw(c5.705,22.118) 9.311,14.977
  text ".designator" at 3.8,6.9 h1.52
